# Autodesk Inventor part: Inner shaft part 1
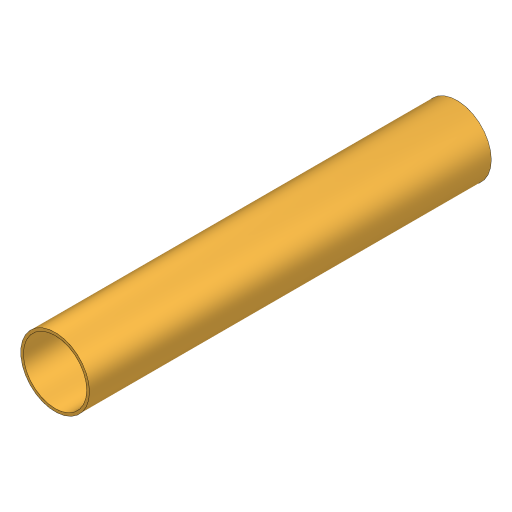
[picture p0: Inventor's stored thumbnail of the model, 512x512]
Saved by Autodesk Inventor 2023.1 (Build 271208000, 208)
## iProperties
Created: 2020-02
Part Number: Inner shaft part 1
Material: Brass, Soft Yellow
Document SubType Name: Modeling
Designer: ftrauzettel
Density: 8.47 g/cm^3
Appearance: Brass - Satin
Sending System: SolidWorks 2016
Last Author: Pam
Last Saved: 2020-02-24
Author: ftrauzettel
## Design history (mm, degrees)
feature "Cut-Extrude1"
body "Solid1"
